Omron CX-Programmer project NuevoProyecto (CX-Programmer 9.50)

# PLC NewPLC1: CP1L-E EM

## Program P16_2 (cyclic task 0)
Local symbols
Etapa_0 10.00 BOOL
Etapa_1 10.01 BOOL
Etapa_2 10.02 BOOL
Etapa_3 10.03 BOOL
Etapa_4 10.04 BOOL
Etapa_5 10.05 BOOL
Etapa_6 10.06 BOOL
Etapa_7 10.07 BOOL
Etapa_8 10.08 BOOL
F1 0.02 BOOL
F2 0.03 BOOL
F3 0.04 BOOL
F4 0.05 BOOL
F5 0.06 BOOL
F6 0.07 BOOL
F7 0.08 BOOL
F8 0.09 BOOL
FSF4 15.00 BOOL
FSF5 15.01 BOOL
FSF6 15.02 BOOL
FSF7 15.03 BOOL
FSF8 15.04 BOOL
KB 100.01 BOOL
KD 100.02 BOOL
KI 100.03 BOOL
KS 100.00 BOOL
PD 0.00 BOOL
PI 0.01 BOOL

### Section Sección1_Programa_principal
; Programa principal (Etapas 0 ... 8)

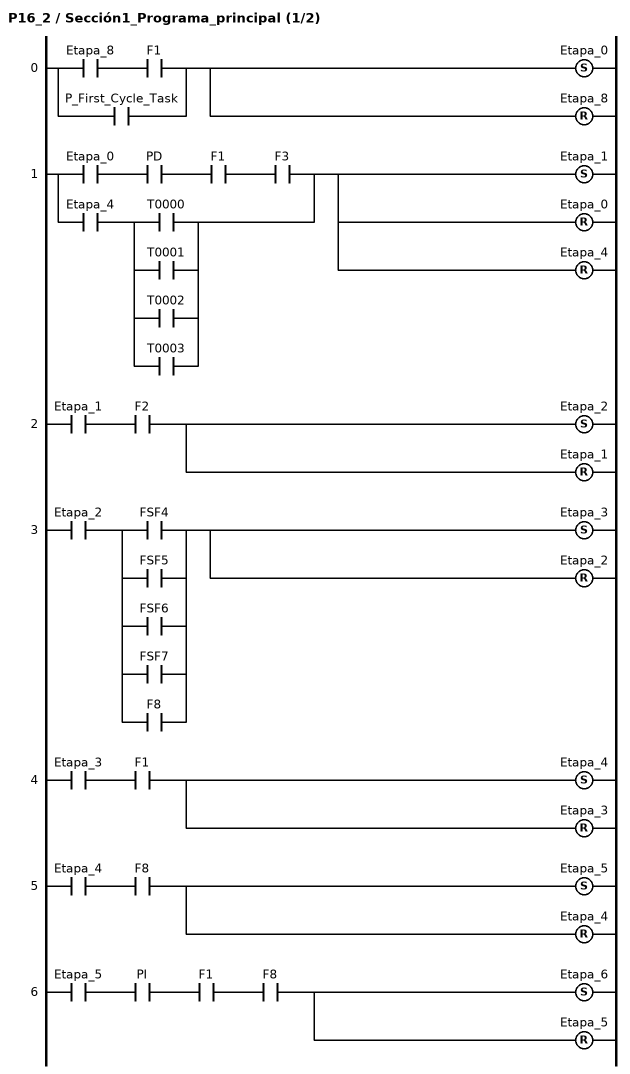
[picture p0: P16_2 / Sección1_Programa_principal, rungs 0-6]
; rung 0
LD Etapa_8
AND F1
OR P_First_Cycle_Task
SET Etapa_0
RSET Etapa_8
; rung 1
LD Etapa_0
AND PD
AND F1
AND F3
LD Etapa_4
LD T0000
OR T0001
OR T0002
OR T0003
ANDLD
ORLD
SET Etapa_1
RSET Etapa_0
RSET Etapa_4
; rung 2
LD Etapa_1
AND F2
SET Etapa_2
RSET Etapa_1
; rung 3
LD Etapa_2
LD FSF4
OR FSF5
OR FSF6
OR FSF7
OR F8
ANDLD
SET Etapa_3
RSET Etapa_2
; rung 4
LD Etapa_3
AND F1
SET Etapa_4
RSET Etapa_3
; rung 5
LD Etapa_4
AND F8
SET Etapa_5
RSET Etapa_4
; rung 6
LD Etapa_5
AND PI
AND F1
AND F8
SET Etapa_6
RSET Etapa_5

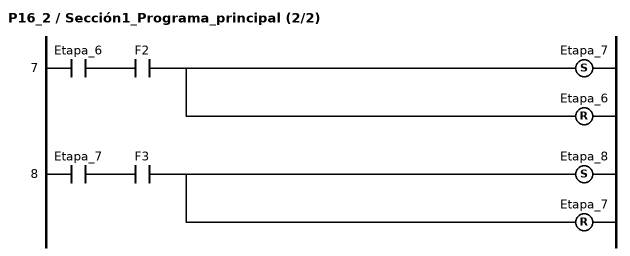
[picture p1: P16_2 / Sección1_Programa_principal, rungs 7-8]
; rung 7
LD Etapa_6
AND F2
SET Etapa_7
RSET Etapa_6
; rung 8
LD Etapa_7
AND F3
SET Etapa_8
RSET Etapa_7

### Section Sección2_Temporizadores

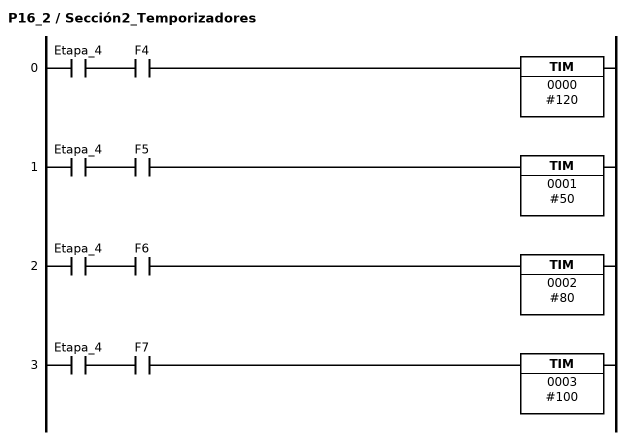
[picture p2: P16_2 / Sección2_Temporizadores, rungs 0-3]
; rung 0
LD Etapa_4
AND F4
TIM 0000 #120
; rung 1
LD Etapa_4
AND F5
TIM 0001 #50
; rung 2
LD Etapa_4
AND F6
TIM 0002 #80
; rung 3
LD Etapa_4
AND F7
TIM 0003 #100

### Section Sección3_Flancos

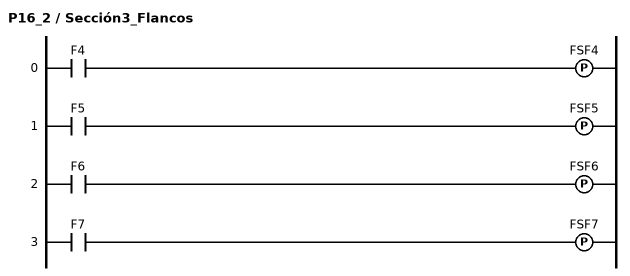
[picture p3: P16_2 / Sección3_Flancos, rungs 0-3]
; rung 0
LD F4
DIFU(013) FSF4
; rung 1
LD F5
DIFU(013) FSF5
; rung 2
LD F6
DIFU(013) FSF6
; rung 3
LD F7
DIFU(013) FSF7

### Section Sección4_Salidas

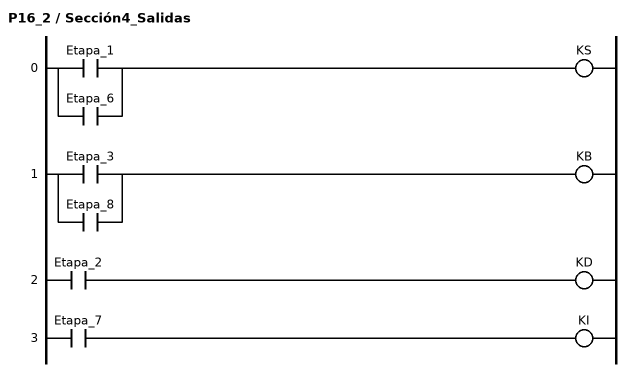
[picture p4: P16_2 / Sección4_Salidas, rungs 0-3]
; rung 0
LD Etapa_1
OR Etapa_6
OUT KS
; rung 1
LD Etapa_3
OR Etapa_8
OUT KB
; rung 2
LD Etapa_2
OUT KD
; rung 3
LD Etapa_7
OUT KI

### Section Sección5_END
; rung 0: Fin de programa
END(001)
